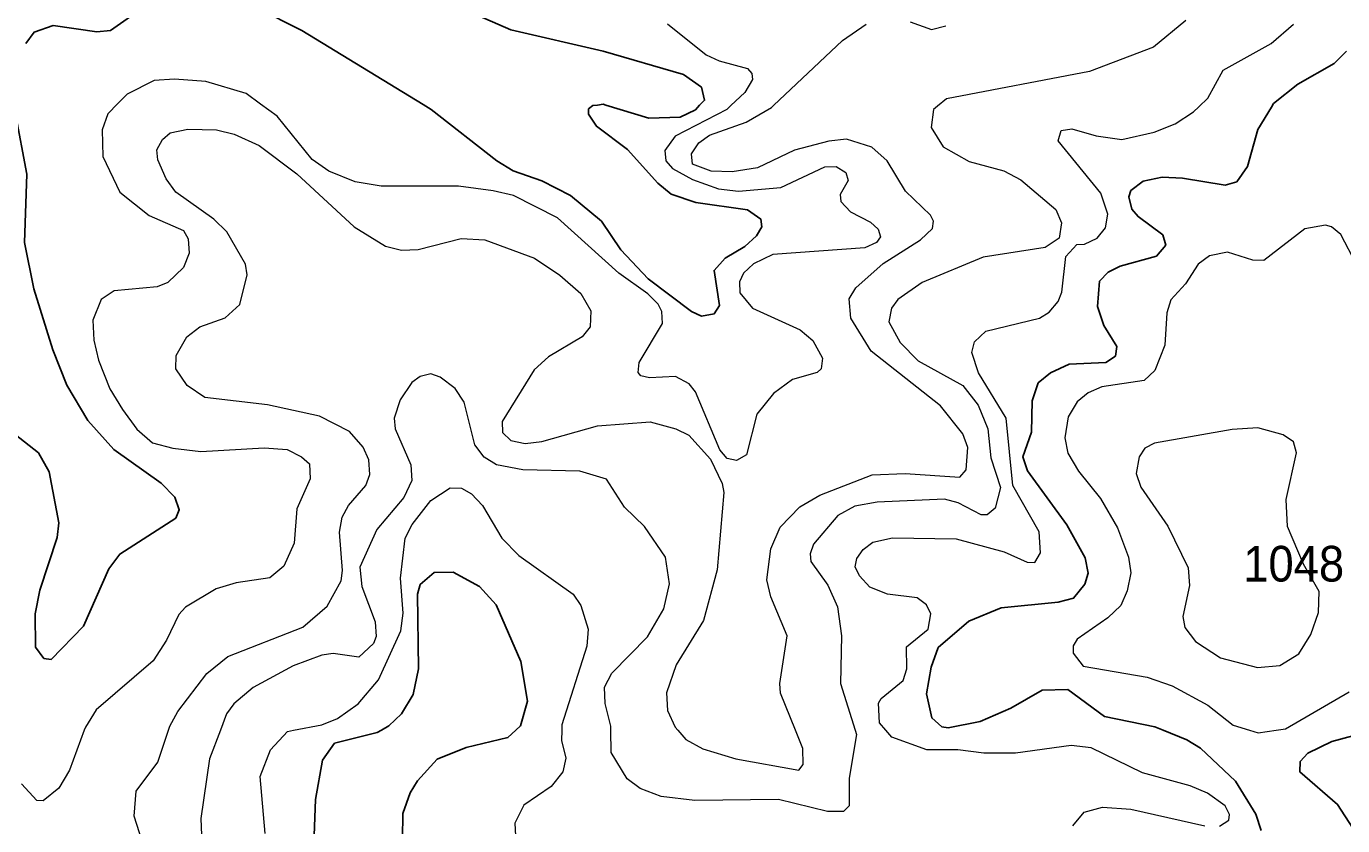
# Model space of a CAD drawing. Extents: x 473.9 to 500, y 7733.1 to 7760.8.
# Drawn here: x 479.198 to 482.147, y 7744.754 to 7746.544 of the extents above; entities that cross this region are included whole.
import ezdxf

# ---------------------------------------------------------------- set-up
doc = ezdxf.new("R2010")
doc.units = 0
doc.header["$LTSCALE"] = 0.032
doc.layers.add('1', color=7, linetype='Continuous', lineweight=25)
doc.layers.add('2', color=7, linetype='Continuous', lineweight=13)
doc.layers.add('21', color=7, linetype='Continuous')

msp = doc.modelspace()

# ---------------------------------------------------------------- linework, layer by layer
at = {"layer": '1'}
for points in [[(479.7143, 7746.5855), (479.8146, 7746.5346), (480.0867, 7746.3689), (480.1046, 7746.358), (480.2517, 7746.2426), (480.2882, 7746.2207), (480.3527, 7746.198), (480.4165, 7746.1654), (480.4861, 7746.1079), (480.53, 7746.0433), (480.5909, 7745.9782), (480.6883, 7745.905), (480.7101, 7745.8948), (480.739, 7745.9003), (480.7505, 7745.9184), (480.7385, 7745.9972), (480.7637, 7746.0251), (480.8072, 7746.0506), (480.8334, 7746.0748), (480.8453, 7746.0951), (480.8431, 7746.1124), (480.8136, 7746.133), (480.6975, 7746.1497), (480.6426, 7746.1682), (480.6126, 7746.193), (480.5444, 7746.2678), (480.475, 7746.3202), (480.4571, 7746.3472), (480.4571, 7746.3591), (480.4668, 7746.3664), (480.4774, 7746.3678), (480.4904, 7746.3694), (480.4959, 7746.3677), (480.5924, 7746.338), (480.6624, 7746.3402), (480.6968, 7746.3573), (480.7062, 7746.3671), (480.7173, 7746.3785), (480.7104, 7746.4075), (480.6697, 7746.436), (480.4904, 7746.4885), (480.283, 7746.5365), (480.0912, 7746.6207)], [(479.1969, 7746.5058), (479.215, 7746.5311), (479.2577, 7746.546), (479.356, 7746.5314), (479.3865, 7746.5349), (479.4739, 7746.596)], [(482.1552, 7746.4886), (482.1275, 7746.4606), (482.0465, 7746.4144), (481.9921, 7746.3709), (481.9873, 7746.3632), (481.9564, 7746.3132), (481.9332, 7746.2302), (481.9096, 7746.196), (481.8839, 7746.1886), (481.7876, 7746.2043), (481.7424, 7746.2059), (481.7002, 7746.1972), (481.6724, 7746.1761), (481.6675, 7746.162), (481.6747, 7746.1345)], [(479.0948, 7745.6905), (479.2253, 7745.5885), (479.249, 7745.546), (479.2704, 7745.432), (479.2672, 7745.3989), (479.2282, 7745.2808), (479.2174, 7745.2284), (479.2186, 7745.1535), (479.2373, 7745.1278), (479.2532, 7745.1255), (479.3255, 7745.2006), (479.3826, 7745.3287), (479.4072, 7745.3618), (479.5328, 7745.4426), (479.5405, 7745.4612), (479.5307, 7745.4892), (479.4996, 7745.5209), (479.394, 7745.596), (479.3356, 7745.6611), (479.2888, 7745.7401), (479.2574, 7745.8191), (479.2145, 7745.9562), (479.1935, 7746.06), (479.1988, 7746.2132), (479.1727, 7746.3519)], [(481.6747, 7746.1345), (481.6884, 7746.1179), (481.7442, 7746.0769), (481.7505, 7746.0536), (481.7295, 7746.0289), (481.6482, 7746.0072), (481.6212, 7745.9933), (481.6023, 7745.9735), (481.5976, 7745.9164), (481.6115, 7745.8738), (481.6405, 7745.8271), (481.6377, 7745.8054), (481.6165, 7745.7909), (481.5338, 7745.7873), (481.4924, 7745.7676), (481.4645, 7745.7454), (481.4509, 7745.7054), (481.4495, 7745.6349), (481.4302, 7745.5796), (481.4408, 7745.5483), (481.5289, 7745.4278), (481.5701, 7745.3535), (481.5765, 7745.3191), (481.5691, 7745.2944), (481.5439, 7745.2629), (481.5094, 7745.2542), (481.3819, 7745.2412), (481.3095, 7745.2115), (481.2406, 7745.1526), (481.2246, 7745.109), (481.2146, 7745.0493), (481.2262, 7744.995), (481.2489, 7744.9748), (481.2632, 7744.9728), (481.3344, 7744.9867), (481.4033, 7745.0172), (481.4732, 7745.0575), (481.5308, 7745.0583), (481.6131, 7744.9985), (481.7263, 7744.9747), (481.7444, 7744.9675), (481.798, 7744.9462), (481.8283, 7744.9273), (481.9067, 7744.8532), (481.9525, 7744.7793), (481.9639, 7744.7429)], [(480.2504, 7745.2482), (480.2133, 7745.2891), (480.1543, 7745.3217), (480.1116, 7745.3206), (480.0801, 7745.2935), (480.0744, 7745.2725), (480.0762, 7745.1052), (480.0642, 7745.0473), (480.0383, 7745.0044), (480.0101, 7744.9776), (479.9931, 7744.9675), (479.9838, 7744.962), (479.8884, 7744.9385), (479.8614, 7744.9007), (479.8454, 7744.8125), (479.8399, 7744.6521)], [(480.0408, 7744.7245), (480.0414, 7744.781), (480.0579, 7744.827), (480.0744, 7744.8542), (480.1184, 7744.9028), (480.1835, 7744.9287), (480.2767, 7744.951), (480.2941, 7744.9675), (480.3047, 7744.9775), (480.3204, 7745.0325), (480.3056, 7745.1211), (480.2504, 7745.2482)], [(482.2729, 7744.5891), (482.1354, 7744.8012), (482.051, 7744.874), (482.0519, 7744.8977), (482.0689, 7744.9158), (482.1226, 7744.9419), (482.2163, 7744.9675)]]:
    msp.add_lwpolyline(points, dxfattribs=at)
at = {"layer": '2'}
for points in [[(481.7956, 7746.5569), (481.7233, 7746.4974), (481.5797, 7746.4428), (481.2594, 7746.3817), (481.2393, 7746.3655), (481.2299, 7746.3579), (481.2251, 7746.3171), (481.2515, 7746.2739), (481.3101, 7746.2412), (481.3877, 7746.2206), (481.4257, 7746.2001), (481.5041, 7746.1338), (481.5167, 7746.1038), (481.5118, 7746.0696), (481.4805, 7746.049), (481.3411, 7746.0271), (481.205, 7745.9706), (481.1503, 7745.9319), (481.136, 7745.9127), (481.1303, 7745.8822), (481.1552, 7745.8356), (481.1958, 7745.7947), (481.2961, 7745.7393), (481.3302, 7745.6953), (481.3519, 7745.6422), (481.3586, 7745.5773), (481.3801, 7745.5109), (481.368, 7745.4648), (481.3507, 7745.4496), (481.3369, 7745.4498), (481.2855, 7745.4771), (481.2548, 7745.4849), (481.1042, 7745.4784), (481.0538, 7745.4692), (481.0159, 7745.4485), (480.9611, 7745.3841), (480.9535, 7745.3625), (480.9553, 7745.3455), (480.9937, 7745.2922), (481.0149, 7745.2439), (481.0239, 7745.1787), (481.0215, 7745.072), (481.0545, 7744.9675), (481.0576, 7744.9577), (481.041, 7744.8601), (481.0409, 7744.7984), (481.0285, 7744.7853), (480.9928, 7744.7851), (480.8832, 7744.8121), (480.6957, 7744.8104), (480.6202, 7744.8191), (480.5727, 7744.8366), (480.5439, 7744.8586), (480.5079, 7744.9172), (480.5071, 7744.9675), (480.507, 7744.9769), (480.4949, 7745.027), (480.4934, 7745.0638), (480.5091, 7745.0952), (480.5897, 7745.1766), (480.6257, 7745.2391), (480.6389, 7745.2954), (480.63, 7745.3554), (480.5826, 7745.424), (480.5377, 7745.4667), (480.4977, 7745.5295), (480.4379, 7745.5476), (480.3098, 7745.5509), (480.2509, 7745.5615), (480.2233, 7745.5789), (480.2029, 7745.6069), (480.1783, 7745.7023), (480.1588, 7745.7326), (480.1251, 7745.7582), (480.1041, 7745.7657)], [(480.6342, 7746.5495), (480.721, 7746.4803), (480.7499, 7746.4667), (480.8134, 7746.4498), (480.8231, 7746.4385), (480.8247, 7746.4249), (480.8078, 7746.3959), (480.7763, 7746.3669), (480.7668, 7746.3581), (480.651, 7746.2978), (480.6285, 7746.2657), (480.6301, 7746.2431), (480.6454, 7746.2255), (480.6904, 7746.2013), (480.7483, 7746.1804), (480.7934, 7746.1748), (480.8882, 7746.1828), (480.9863, 7746.2295), (481.0121, 7746.2303), (481.0338, 7746.2166), (481.0386, 7746.1989), (481.0209, 7746.1676), (481.0225, 7746.1515), (481.0442, 7746.1282), (481.0892, 7746.1057), (481.1061, 7746.0896), (481.1117, 7746.0727), (481.1021, 7746.0598), (481.0764, 7746.0478), (480.8705, 7746.0333), (480.8271, 7746.0124), (480.8046, 7745.9915), (480.7958, 7745.9714), (480.7966, 7745.9473), (480.8247, 7745.9127), (480.9317, 7745.8645), (480.9598, 7745.8403), (480.9815, 7745.8009), (480.9783, 7745.7768), (480.9694, 7745.7688), (480.914, 7745.7527), (480.8713, 7745.7213), (480.8344, 7745.6755), (480.811, 7745.5839), (480.7885, 7745.5718), (480.7676, 7745.5758), (480.7515, 7745.5951), (480.6969, 7745.7254), (480.6824, 7745.743), (480.6519, 7745.7599), (480.594, 7745.7567), (480.5747, 7745.7615), (480.5682, 7745.7688), (480.5706, 7745.7913), (480.6229, 7745.8781), (480.6213, 7745.9055), (480.6132, 7745.9215), (480.5899, 7745.9449), (480.5248, 7745.9915), (480.3881, 7746.1153), (480.2892, 7746.1652), (480.2434, 7746.1756), (480.1662, 7746.1861), (479.9926, 7746.1861), (479.9347, 7746.1957), (479.8752, 7746.2198), (479.8382, 7746.2456), (479.7594, 7746.3429), (479.7224, 7746.37), (479.6903, 7746.3935), (479.6002, 7746.4208), (479.5295, 7746.4257), (479.4844, 7746.4224), (479.4233, 7746.3919), (479.4031, 7746.371), (479.3807, 7746.3477), (479.3678, 7746.3123), (479.3694, 7746.2528), (479.4072, 7746.1724), (479.4732, 7746.1201), (479.5495, 7746.0864), (479.56, 7746.0679), (479.5624, 7746.0357), (479.5495, 7746.0036), (479.515, 7745.9706), (479.4909, 7745.9609), (479.3944, 7745.9513), (479.3654, 7745.932), (479.3469, 7745.8862), (479.3493, 7745.8411), (479.3598, 7745.7961)], [(481.0447, 7745.8904), (481.0408, 7745.9339), (481.0559, 7745.9581), (481.1172, 7746.0125), (481.2009, 7746.0657), (481.2277, 7746.0913), (481.2298, 7746.1079), (481.2234, 7746.1208), (481.1672, 7746.1748), (481.1265, 7746.2427), (481.0919, 7746.273), (481.0351, 7746.2912), (480.9954, 7746.2871), (480.9187, 7746.2664), (480.8356, 7746.2273), (480.7788, 7746.2182), (480.7317, 7746.2196), (480.6903, 7746.2352), (480.6879, 7746.2586), (480.7044, 7746.2829), (480.728, 7746.3002), (480.8104, 7746.3296), (480.8672, 7746.362), (480.872, 7746.3666), (481.026, 7746.512), (481.0794, 7746.5486)], [(481.2143, 7745.2484), (481.1937, 7745.2637), (481.1271, 7745.2725), (481.0876, 7745.2882), (481.0643, 7745.3129), (481.0547, 7745.3334), (481.0587, 7745.3522), (481.0724, 7745.3723), (481.0942, 7745.3883), (481.1384, 7745.3982), (481.2812, 7745.3961), (481.3882, 7745.3667), (481.4402, 7745.3438), (481.457, 7745.3433), (481.4696, 7745.3651), (481.467, 7745.4117), (481.4081, 7745.5157), (481.3931, 7745.6664), (481.3306, 7745.7682), (481.316, 7745.8132), (481.3222, 7745.8373), (481.3474, 7745.8615), (481.4679, 7745.8902), (481.4895, 7745.9039), (481.5092, 7745.9275), (481.5176, 7745.9488), (481.5265, 7746.0288), (481.5514, 7746.0551), (481.5681, 7746.0559), (481.5968, 7746.0692), (481.6153, 7746.0929), (481.6205, 7746.1233), (481.6048, 7746.1702), (481.5091, 7746.2876), (481.5161, 7746.3108), (481.54, 7746.3146), (481.5947, 7746.2988), (481.6518, 7746.2907), (481.7243, 7746.3067), (481.7716, 7746.3255), (481.8128, 7746.3522), (481.8248, 7746.3637), (481.8449, 7746.383), (481.8789, 7746.4459), (481.9863, 7746.5053), (482.0367, 7746.5492)], [(481.178, 7746.554), (481.2258, 7746.5366), (481.2575, 7746.5454)], [(479.5162, 7744.9675), (479.5192, 7744.9765), (479.5371, 7745.0092), (479.6021, 7745.0945), (479.6494, 7745.1324), (479.8174, 7745.1981), (479.8719, 7745.2451), (479.9032, 7745.3024), (479.9064, 7745.3249), (479.8993, 7745.4112), (479.9054, 7745.4443), (479.9193, 7745.4706), (479.9585, 7745.5153), (479.9675, 7745.5404), (479.9654, 7745.573), (479.9526, 7745.6011), (479.9216, 7745.6365), (479.8543, 7745.6705), (479.7384, 7745.6963), (479.5975, 7745.713), (479.5582, 7745.7398), (479.5325, 7745.7767), (479.5332, 7745.8068), (479.5576, 7745.8484), (479.5867, 7745.8706), (479.6435, 7745.8909), (479.6758, 7745.921), (479.6925, 7745.9874), (479.6886, 7746.0114), (479.6467, 7746.0839), (479.6178, 7746.112), (479.5325, 7746.1729), (479.5111, 7746.2024), (479.4925, 7746.2452), (479.49, 7746.2672), (479.5026, 7746.2909), (479.5203, 7746.3051), (479.5593, 7746.3138), (479.6237, 7746.3122), (479.6634, 7746.3026), (479.7197, 7746.2773), (479.804, 7746.2137), (479.9322, 7746.0951), (480.0022, 7746.0519), (480.038, 7746.043), (480.0757, 7746.0445), (480.1716, 7746.0687), (480.225, 7746.0659), (480.3361, 7746.0246), (480.3929, 7745.9866), (480.44, 7745.9457), (480.4624, 7745.907), (480.4613, 7745.8709), (480.4428, 7745.8487), (480.3673, 7745.8039), (480.3354, 7745.7749), (480.2638, 7745.6588), (480.2643, 7745.6345), (480.2834, 7745.6164), (480.3153, 7745.6096), (480.3527, 7745.6144), (480.4774, 7745.6492), (480.5955, 7745.6585), (480.6529, 7745.6426), (480.6823, 7745.628), (480.7305, 7745.5742), (480.7568, 7745.52), (480.7603, 7745.5001), (480.7458, 7745.3265), (480.7145, 7745.2134), (480.6539, 7745.1138), (480.6317, 7745.0511), (480.6344, 7745.0119), (480.6516, 7744.9742), (480.6573, 7744.9675), (480.6751, 7744.9468), (480.7136, 7744.9259), (480.7874, 7744.9035), (480.9282, 7744.8777), (480.938, 7744.8909), (480.937, 7744.9266), (480.9206, 7744.9675), (480.8875, 7745.0504), (480.8859, 7745.0719), (480.9021, 7745.1792), (480.8655, 7745.2659), (480.8569, 7745.3046), (480.866, 7745.3736), (480.8863, 7745.4223), (480.9307, 7745.468), (480.9758, 7745.4937), (481.093, 7745.5397), (481.1669, 7745.5427), (481.2889, 7745.534), (481.3036, 7745.5507), (481.3069, 7745.6004), (481.296, 7745.6315), (481.2459, 7745.6943), (481.0904, 7745.8165), (481.0447, 7745.8904)], [(482.1775, 7746.0103), (482.1428, 7746.0778), (482.1218, 7746.0952), (482.1081, 7746.0984), (482.0619, 7746.0903), (481.9698, 7746.0198), (481.9452, 7746.0203), (481.8889, 7746.038), (481.8481, 7746.03), (481.8231, 7746.0114), (481.795, 7745.9675), (481.7615, 7745.9314), (481.7525, 7745.9022), (481.7484, 7745.8298), (481.7263, 7745.7731), (481.7022, 7745.7511), (481.6075, 7745.7365), (481.5763, 7745.7228), (481.552, 7745.703), (481.5318, 7745.6696), (481.5241, 7745.6226), (481.5312, 7745.5881), (481.5548, 7745.5479), (481.6039, 7745.4867), (481.6425, 7745.4208), (481.6673, 7745.3549), (481.6721, 7745.3201), (481.664, 7745.2799), (481.6496, 7745.2468), (481.621, 7745.2191), (481.5516, 7745.1713), (481.5429, 7745.1563), (481.5429, 7745.1397), (481.5655, 7745.111), (481.7088, 7745.086), (481.765, 7745.0665), (481.8445, 7745.0236), (481.9013, 7744.9784), (481.9379, 7744.9675), (481.9571, 7744.9618), (481.9979, 7744.9675), (482.0186, 7744.9704), (482.1612, 7745.0537)], [(479.3598, 7745.7961), (479.3847, 7745.7318), (479.4129, 7745.686), (479.445, 7745.6417), (479.4804, 7745.6112), (479.5262, 7745.5991), (479.5889, 7745.5919), (479.7305, 7745.5999), (479.7819, 7745.5959), (479.8141, 7745.5798), (479.8318, 7745.5638), (479.8334, 7745.5308), (479.8036, 7745.4633), (479.798, 7745.3861), (479.7747, 7745.3346), (479.7433, 7745.3089), (479.6677, 7745.2976), (479.6227, 7745.284), (479.5544, 7745.2429), (479.5391, 7745.2269), (479.5118, 7745.169), (479.482, 7745.1231), (479.3542, 7745.013), (479.33, 7744.9744), (479.3275, 7744.9675), (479.2947, 7744.8779), (479.2705, 7744.8377), (479.2352, 7744.8096), (479.2215, 7744.8104), (479.1869, 7744.8474)], [(480.1041, 7745.7657), (480.0799, 7745.76), (480.0617, 7745.7462), (480.0352, 7745.7076), (480.0222, 7745.6661), (480.0241, 7745.6428), (480.0591, 7745.5618), (480.0617, 7745.5269), (480.0436, 7745.4884), (479.983, 7745.4171), (479.9452, 7745.3324), (479.9496, 7745.289), (479.9789, 7745.2102), (479.9812, 7745.1774), (479.9753, 7745.162), (479.9426, 7745.1313), (479.8848, 7745.1391), (479.8601, 7745.1358), (479.7957, 7745.1115), (479.7058, 7745.0632), (479.6626, 7745.0263), (479.6461, 7745.0039), (479.6324, 7744.9675), (479.6081, 7744.9031), (479.5889, 7744.7697), (479.5909, 7744.7136)], [(479.7327, 7744.7358), (479.7216, 7744.8638), (479.7447, 7744.9238), (479.7825, 7744.9649), (479.7964, 7744.9675), (479.8595, 7744.9793), (479.895, 7744.994), (479.9411, 7745.0268), (479.9868, 7745.0805), (480.0368, 7745.1903), (480.0423, 7745.23), (480.036, 7745.3077), (480.0463, 7745.3979), (480.062, 7745.4283), (480.1036, 7745.4817), (480.1473, 7745.5107), (480.1727, 7745.5098), (480.1951, 7745.4969), (480.2195, 7745.4709), (480.2634, 7745.3976), (480.3012, 7745.3586), (480.4231, 7745.2722), (480.4403, 7745.2468), (480.4566, 7745.1937), (480.4538, 7745.1556), (480.3971, 7744.9797), (480.3971, 7744.9675), (480.397, 7744.9443), (480.4064, 7744.9052), (480.3997, 7744.874), (480.3739, 7744.8412), (480.3126, 7744.7998), (480.2919, 7744.759), (480.2955, 7744.7032)], [(481.8711, 7744.7526), (481.8919, 7744.7659), (481.8936, 7744.7789), (481.8837, 7744.7982), (481.844, 7744.8261), (481.8054, 7744.8427), (481.698, 7744.872), (481.583, 7744.9277), (481.5385, 7744.9332), (481.414, 7744.9157), (481.3427, 7744.9157), (481.2848, 7744.9237), (481.2151, 7744.9238), (481.1367, 7744.9521), (481.1236, 7744.9675), (481.1093, 7744.9842), (481.107, 7745.0279), (481.1126, 7745.0388), (481.1625, 7745.0785), (481.1703, 7745.1046), (481.1697, 7745.1542), (481.218, 7745.1939), (481.2239, 7745.2278), (481.2143, 7745.2484)], [(479.1414, 7744.1801), (479.4627, 7744.2654), (479.485, 7744.278), (479.5569, 7744.343), (479.5638, 7744.384), (479.5166, 7744.5064), (479.5061, 7744.5562), (479.5157, 7744.6168), (479.463, 7744.7005), (479.4394, 7744.775), (479.4435, 7744.8311), (479.4926, 7744.896), (479.5162, 7744.9675)], [(481.5426, 7744.7533), (481.5677, 7744.7838), (481.6085, 7744.795), (481.6724, 7744.7903), (481.838, 7744.7534)]]:
    msp.add_lwpolyline(points, dxfattribs=at)
msp.add_lwpolyline([(482.0231, 7745.4234), (482.02, 7745.4843), (482.0435, 7745.5886), (482.0369, 7745.6135), (482.0138, 7745.6288), (481.9564, 7745.6448), (481.899, 7745.641), (481.7253, 7745.6106), (481.7035, 7745.5989), (481.6912, 7745.5801), (481.6842, 7745.5425), (481.6947, 7745.5116), (481.7551, 7745.4246), (481.8006, 7745.3313), (481.8039, 7745.2913), (481.7888, 7745.2218), (481.7931, 7745.1976), (481.8169, 7745.1665), (481.8728, 7745.1294), (481.9559, 7745.1079), (482.0059, 7745.1122), (482.0484, 7745.1385), (482.0758, 7745.1819), (482.0927, 7745.231), (482.0941, 7745.2782), (482.0589, 7745.3391)], close=True, dxfattribs=at)

# ---------------------------------------------------------------- texts
at = {"layer": '21', "width": 0.95}
msp.add_text('1048', height=0.08, dxfattribs=at).set_placement((481.924, 7745.3004))

doc.saveas('drawing.dxf')
